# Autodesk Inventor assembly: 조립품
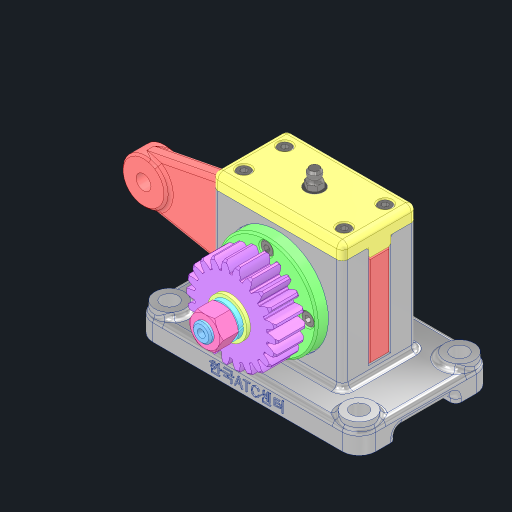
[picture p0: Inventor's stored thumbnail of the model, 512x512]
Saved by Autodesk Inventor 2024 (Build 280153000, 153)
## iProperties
Created: 2025-04
Part Number: 조립품
Document SubType Name: Assembly
Designer: kh_501
Author: kh_501
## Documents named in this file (15)
- C:\Users\kh_501\Desktop\750404V1010\조립품.iam
- C:\Users\kh_501\Desktop\750404V1010\본체.ipt
- C:\Users\kh_501\Desktop\750404V1010\그리스 니플 M6x0.75\그리스 니플 M6x0.75.ipt
- C:\Users\kh_501\Desktop\750404V1010\로드\로드.ipt
- C:\Users\kh_501\Desktop\750404V1010\스퍼기어\스퍼기어.ipt
- C:\Users\kh_501\Desktop\750404V1010\스프링와셔 M10\스프링와셔 M10.ipt
- C:\Users\kh_501\Desktop\750404V1010\실링\실링.ipt
- C:\Users\kh_501\Desktop\750404V1010\앞커버\앞커버.ipt
- C:\Users\kh_501\Desktop\750404V1010\윗커버\윗커버.ipt
- C:\Users\kh_501\Desktop\750404V1010\육각 너트 M10\육각 너트 M10.ipt
- C:\Users\kh_501\Desktop\750404V1010\육각 소켓 머리 볼트 M4x10\육각 소켓 머리 볼트 M4x10.ipt
- C:\Users\kh_501\Desktop\750404V1010\편심축\편심축.ipt
- C:\Users\kh_501\Desktop\750404V1010\평와셔 M10\평와셔 M10.ipt
- C:\Users\kh_501\Desktop\750404V1010\평행키 4x4x10\평행키 4x4x10.ipt
- C:\Users\kh_501\Desktop\750404V1010\플랜지 오일레스 부시\플랜지 오일레스 부시.ipt
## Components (3 placed, 2 different names)
1. 그리스 니플 M6x0.75:1 — 각도:3
2. 플랜지 오일레스 부시:1 — 각도:9
3. 플랜지 오일레스 부시:2 — 각도:10
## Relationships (3: Angle 3)
- 각도:3 [Angle]: 그리스 니플 M6x0.75:1
- 각도:9 [Angle]: 플랜지 오일레스 부시:1
- 각도:10 [Angle]: 플랜지 오일레스 부시:2
